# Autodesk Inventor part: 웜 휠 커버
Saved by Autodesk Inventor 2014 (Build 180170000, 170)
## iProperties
Created: 2026-07
Part Number: 웜 휠 커버
Material: 일반
Document SubType Name: Modeling
Designer: dg
Density: 1 g/cm^3
Appearance: 기본값
Author: dg
Author: jhkim
Creation Date: 2026-07-02
Sending System: Autodesk Inventor 2027
Preprocessor: ST-DEVELOPER v20.1
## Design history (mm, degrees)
node "웜 휠 커버1"
node "솔리드1"
node "기준1"
